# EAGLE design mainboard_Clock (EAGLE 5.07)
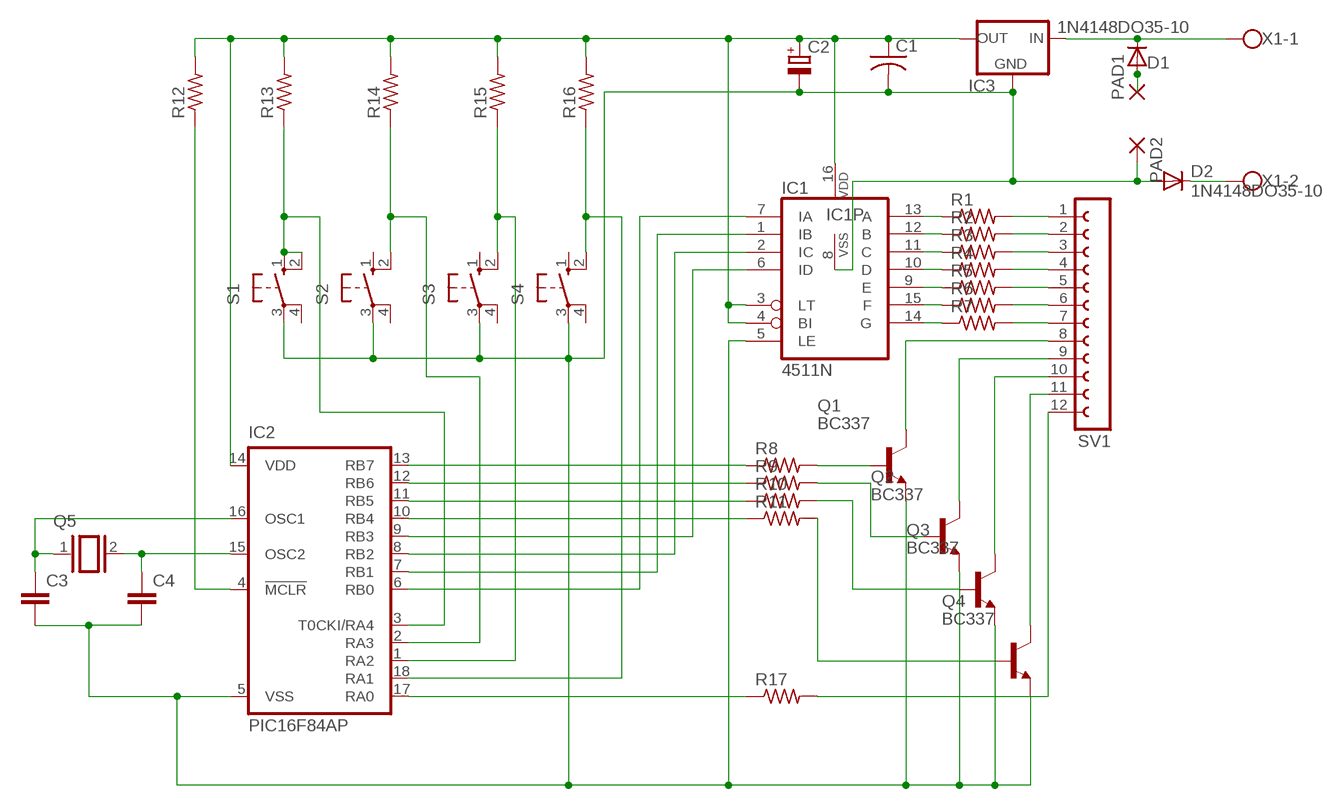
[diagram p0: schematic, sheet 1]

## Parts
C1  C-US050-025X075  [C050-025X075]
C2  CPOL-EUE5-8.5  [E5-8,5]
C3  C2.5/2  [C2.5-2]
C4  C2.5/2  [C2.5-2]
D1  1N4148DO35-10  [DO35-10]
D2  1N4148DO35-10  [DO35-10]
IC1  4511N  [DIL16]
IC2  PIC16F84AP  [DIL18]
IC3  78XXS  [78XXS]
PAD1  3,81/1,4  [3,81/1,4]
PAD2  3,81/1,4  [3,81/1,4]
Q1  BC337  [TO92]
Q2  BC337  [TO92]
Q3  BC337  [TO92]
Q4  BC337  [TO92]
Q5  XTAL/S  [QS]
R1  R-US_0207/10  [0207/10]
R2  R-US_0207/10  [0207/10]
R3  R-US_0207/10  [0207/10]
R4  R-US_0207/10  [0207/10]
R5  R-US_0207/10  [0207/10]
R6  R-US_0207/10  [0207/10]
R7  R-US_0207/10  [0207/10]
R8  R-US_0207/10  [0207/10]
R9  R-US_0207/10  [0207/10]
R10  R-US_0207/10  [0207/10]
R11  R-US_0207/10  [0207/10]
R12  R-US_0207/10  [0207/10]
R13  R-US_0207/10  [0207/10]
R14  R-US_0207/10  [0207/10]
R15  R-US_0207/10  [0207/10]
R16  R-US_0207/10  [0207/10]
R17  R-US_0207/10  [0207/10]
S1  10-XX  [B3F-10XX]
S2  10-XX  [B3F-10XX]
S3  10-XX  [B3F-10XX]
S4  10-XX  [B3F-10XX]
SV1  FE12-1  [FE12]
X1  W237-102  [W237-102]

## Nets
N$1: Q1.3(C) SV1.8
N$2: Q3.2(B) R10.2
N$3: Q3.3(C) SV1.10
N$4: IC2.11(RB5) R10.1
N$5: IC1.13(A) R1.1
N$6: IC1.12(B) R2.1
N$7: IC1.11(C) R3.1
N$8: IC1.10(D) R4.1
N$9: IC1.9(E) R5.1
N$10: IC1.15(F) R6.1
N$11: IC1.14(G) R7.1
N$12: Q1.2(B) R8.2
N$13: Q2.2(B) R9.2
N$14: Q4.3(C) SV1.11
N$23: R1.2 SV1.1
N$24: IC2.13(RB7) R8.1
N$25: IC2.12(RB6) R9.1
N$26: Q2.3(C) SV1.9
N$28: C1.1 C2.+ IC1.3(LT) IC1.4(BI) IC1.16(VDD) IC2.14(VDD) IC3.OUT R12.2 R13.2 R14.2 R15.2 R16.2
N$29: IC1.7(IA) IC2.6(RB0)
N$30: IC1.1(IB) IC2.7(RB1)
N$31: IC1.2(IC) IC2.8(RB2)
N$32: IC1.6(ID) IC2.9(RB3)
N$33: Q4.2(B) R11.2
N$34: C1.2 C2.- C3.2 C4.2 D2.A IC1.5(LE) IC1.8(VSS) IC2.5(VSS) IC3.GND PAD2.1(P) Q1.1(E) Q2.1(E) Q3.1(E) Q4.1(E) S1.3(P) S2.3(P) S3.3(P) S4.3(P)
N$35: D1.C IC3.IN X1.1
N$36: D1.A PAD1.1(P)
N$37: D2.C X1.2
N$38: IC2.17(RA0) R17.1
N$39: IC2.4(!MCLR) R12.1
N$40: IC2.3(T0CKI/RA4) R13.1 S1.1(S) S1.2(S1)
N$41: IC2.2(RA3) R14.1 S2.2(S1)
N$42: IC2.1(RA2) R15.1 S3.2(S1)
N$43: IC2.18(RA1) R16.1 S4.2(S1)
N$45: C4.1 IC2.15(OSC2) Q5.2
N$46: C3.1 IC2.16(OSC1) Q5.1
N$47: R2.2 SV1.2
N$48: R3.2 SV1.3
N$49: R4.2 SV1.4
N$50: R5.2 SV1.5
N$51: R6.2 SV1.6
N$52: R7.2 SV1.7
N$56: IC2.10(RB4) R11.1
N$57: R17.2 SV1.12
Unconnected: S1.4(P1) S2.1(S) S2.4(P1) S3.1(S) S3.4(P1) S4.1(S) S4.4(P1)

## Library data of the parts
C1 = resistor:C-US: CAPACITOR, American symbol
C2 = resistor:CPOL-EU: POLARIZED CAPACITOR, European symbol
C3 C4 = capacitor-wima:C: CAPACITOR
D1 D2 = diode:1N4148: DIODE
IC1 = 45xx:4511: BCD to 7-segment LATCH/DECODER/DRIVER
IC2 = microchip:PIC16F8*: MICROCONTROLLER 8-Bit PIC16F8X Family - CMOS Flash/EEPROM Pin Compatible : PIC16F83, PIC16CR83, PIC16F84A, PIC16CR84 see also PIC16C*
IC3 = v-reg:78XXS: VOLTAGE REGULATOR
PAD1 PAD2 = wirepad:3,81/1,4: THROUGH-HOLE PAD
Q1-Q4 = transistor-npn:BC337*: NPN Transistor
Q5 = special:XTAL/S: CRYSTAL
R1-R17 = resistor:R-US_: RESISTOR, American symbol
S1-S4 = switch-omron:10-XX: OMRON SWITCH
SV1 = con-lsta:FE12-1: FEMALE HEADER
X1 = con-wago-500:W237-102: WAGO SCREW CLAMP

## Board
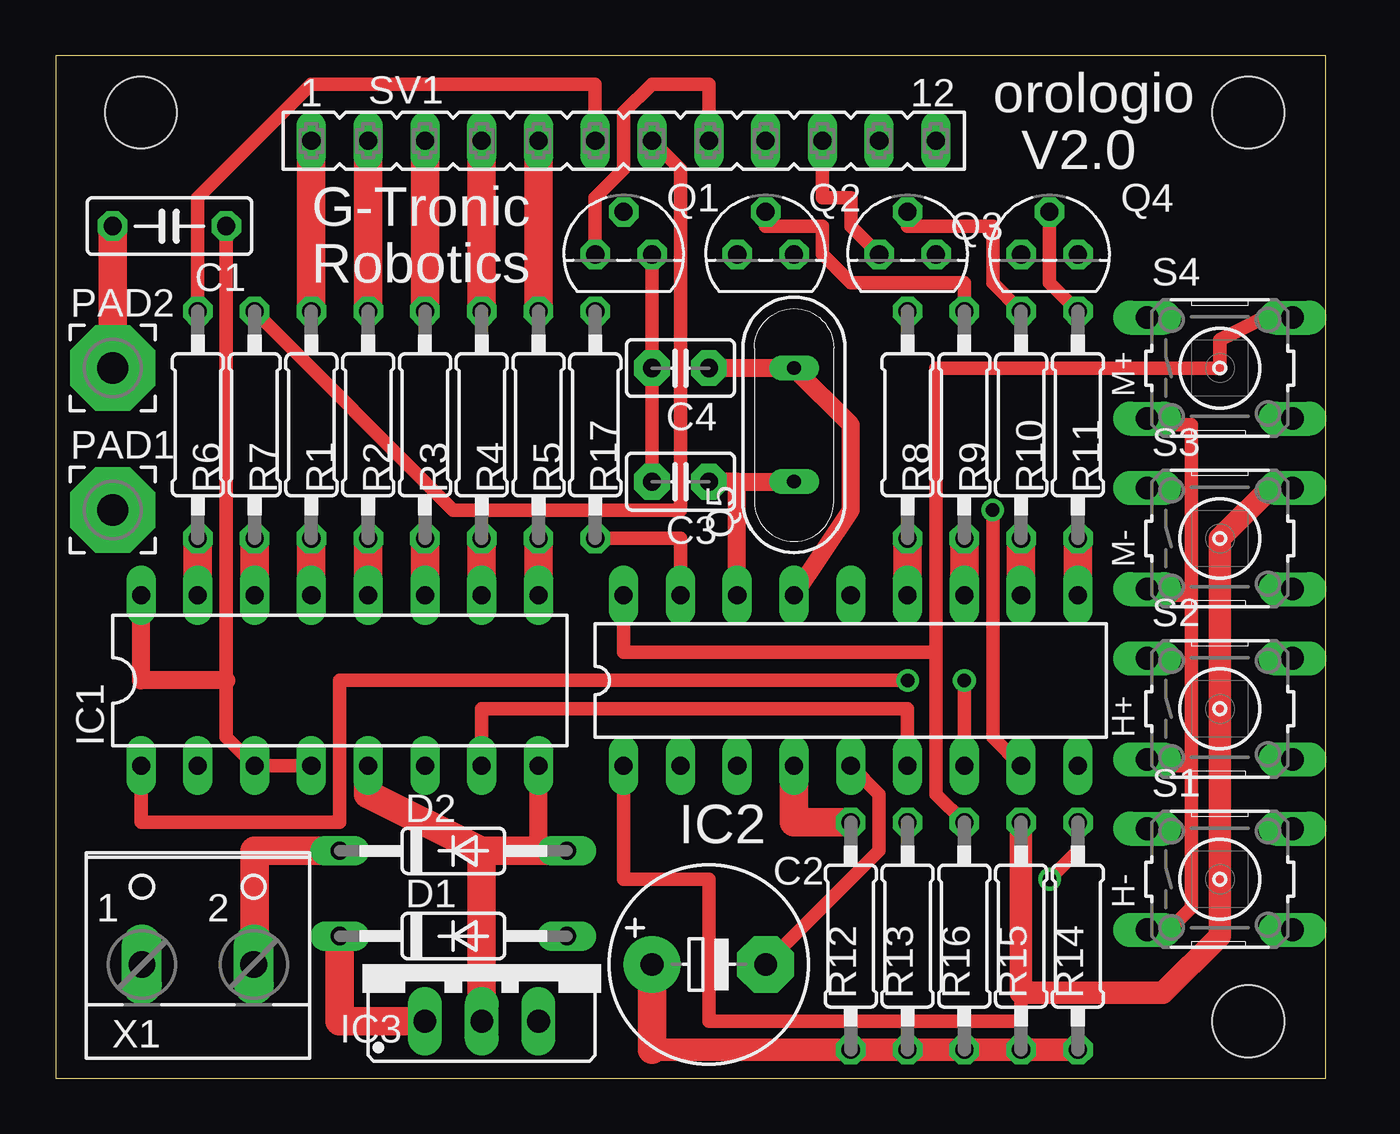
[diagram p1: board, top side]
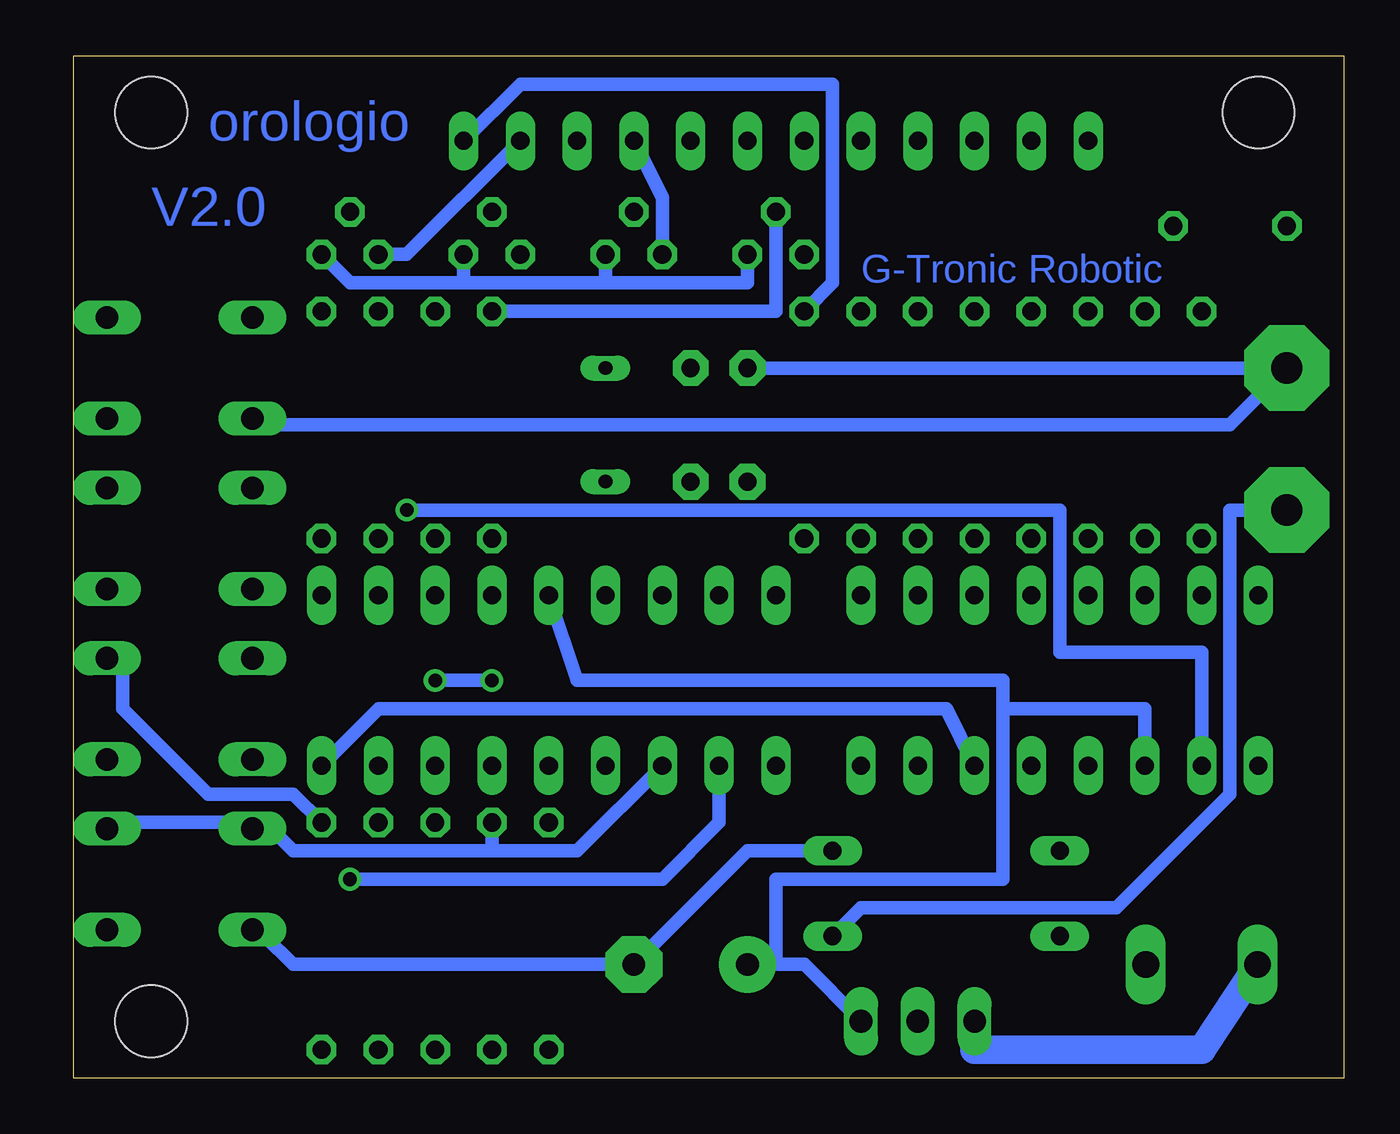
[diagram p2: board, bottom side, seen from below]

Size 56.82 x 45.71 mm. Coordinates in mm from the lower left corner, seen from the top.
Outline: 0,0 56.82,0 56.82,45.71 0,45.71 0,0
Copper layers (1*16): Top 0.035mm / dielectric 1.5mm / Bottom 0.035mm
Design rules "default": minimum track width 10mil, minimum drill 24mil, track to track 8mil, track to pad 8mil, pad to pad 8mil, via to via 8mil, smd to smd 8mil, copper to edge 40mil, drill to drill 8mil, minimum pad ring 10mil, minimum via ring 8mil, stop-mask expansion 4mil, vias tented up to drill 0mil, thermal gap 10mil
Holes 3.2 mm at 53.34,43.18 3.81,43.18 53.34,2.54

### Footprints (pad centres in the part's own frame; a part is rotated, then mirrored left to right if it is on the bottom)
C050-025X075 = drill 0.813 octagon: 1 -2.54,0; 2 2.54,0
E5-8,5 = drill 1.016 pad 2.54 round: + -2.54,0 | drill 1.016 pad 2.54 octagon: - 2.54,0
C2.5-2 = drill 0.813 pad 1.6 octagon: 1 -1.27,0; 2 1.27,0
DO35-10 = drill 0.813 long: A 5.08,0; C -5.08,0
DIL16 = drill 0.813 long: 1 -8.89,-3.81; 2 -6.35,-3.81; 3 -3.81,-3.81; 4 -1.27,-3.81; 5 1.27,-3.81; 6 3.81,-3.81; 7 6.35,-3.81; 8 8.89,-3.81; 9 8.89,3.81; 10 6.35,3.81; 11 3.81,3.81; 12 1.27,3.81; 13 -1.27,3.81; 14 -3.81,3.81; 15 -6.35,3.81; 16 -8.89,3.81
DIL18 = drill 0.813 long: 1 -10.16,-3.81; 2 -7.62,-3.81; 3 -5.08,-3.81; 4 -2.54,-3.81; 5 0,-3.81; 6 2.54,-3.81; 7 5.08,-3.81; 8 7.62,-3.81; 9 10.16,-3.81; 10 10.16,3.81; 11 7.62,3.81; 12 5.08,3.81; 13 2.54,3.81; 14 0,3.81; 15 -2.54,3.81; 16 -5.08,3.81; 17 -7.62,3.81; 18 -10.16,3.81
78XXS = drill 1.016 long: GND 0,-2.54; IN -2.54,-2.54; OUT 2.54,-2.54
3,81/1,4 = drill 1.397 pad 3.81 octagon: 1 0,0
TO92 = drill 0.813 octagon: 1 1.27,0; 2 0,1.905; 3 -1.27,0
QS = drill 0.61 long: 1 -2.54,0; 2 2.54,0
0207/10 = drill 0.813 octagon: 1 -5.08,0; 2 5.08,0
B3F-10XX = drill 1.016 long: 1 -3.251,2.261; 2 3.251,2.261; 3 -3.251,-2.261; 4 3.251,-2.261
FE12 = drill 0.813 long: 1 -13.97,0; 2 -11.43,0; 3 -8.89,0; 4 -6.35,0; 5 -3.81,0; 6 -1.27,0; 7 1.27,0; 8 3.81,0; 9 6.35,0; 10 8.89,0; 11 11.43,0; 12 13.97,0
W237-102 = drill 1.194 long: 1 -2.5,-1.27; 2 2.5,-1.27

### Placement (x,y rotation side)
C1  5.08,38.1 180 top
C2  29.21,5.08 0 top
C3  27.94,26.67 180 top
C4  27.94,31.75 180 top
D1  17.78,6.35 0 top
D2  17.78,10.16 0 top
IC1  12.7,17.78 0 top
IC2  35.56,17.78 0 top
IC3  19.05,5.08 0 top
PAD1  2.54,25.4 0 top
PAD2  2.54,31.75 0 top
Q1  25.4,36.83 0 top
Q2  31.75,36.83 0 top
Q3  38.1,36.83 0 top
Q4  44.45,36.83 0 top
Q5  33.02,29.21 90 top
R1  11.43,29.21 90 top
R2  13.97,29.21 90 top
R3  16.51,29.21 90 top
R4  19.05,29.21 90 top
R5  21.59,29.21 90 top
R6  6.35,29.21 90 top
R7  8.89,29.21 90 top
R8  38.1,29.21 90 top
R9  40.64,29.21 90 top
R10  43.18,29.21 90 top
R11  45.72,29.21 90 top
R12  35.56,6.35 270 top
R13  38.1,6.35 270 top
R14  45.72,6.35 270 top
R15  43.18,6.35 270 top
R16  40.64,6.35 270 top
R17  24.13,29.21 90 top
S1  52.07,8.89 0 top
S2  52.07,16.51 0 top
S3  52.07,24.13 0 top
S4  52.07,31.75 0 top
SV1  25.4,41.91 0 top
X1  6.35,6.35 0 top

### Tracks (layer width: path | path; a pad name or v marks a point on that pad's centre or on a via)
N$1
  Top 0.61: Q1.3 24.13,39.37 25.4,40.64 25.4,43.18 26.67,44.45 29.21,44.45 SV1.8
N$2
  Top 0.61: R10.2 41.91,35.56 41.91,38.1 38.1,38.1 Q3.2
N$3
  Top 0.61: Q3.3 35.56,38.1 35.56,39.37 34.29,39.37 SV1.10
N$4
  Top 1.27: IC2.11 R10.1
N$5
  Top 1.27: IC1.13 R1.1
N$6
  Top 1.27: IC1.12 R2.1
N$7
  Top 1.27: IC1.11 R3.1
N$8
  Top 1.27: IC1.10 R4.1
N$9
  Top 1.27: IC1.9 R5.1
N$10
  Top 1.27: IC1.15 R6.1
N$11
  Top 1.27: IC1.14 R7.1
N$12
  Bottom 0.61: R8.2 25.4,34.29 Q1.2
N$13
  Top 0.61: R9.2 40.64,35.56 35.56,35.56 34.29,36.83 34.29,38.1 31.75,38.1 Q2.2
N$14
  Bottom 0.61: SV1.11 41.91,36.83 Q4.3
N$23
  Top 1.27: R1.2 SV1.1
N$24
  Top 1.27: IC2.13 R8.1
N$25
  Top 1.27: IC2.12 R9.1
N$26
  Bottom 0.61: Q2.3 30.48,39.37 SV1.9
N$28
  Top 0.61: C1.1 7.62,17.78 7.62,15.24 IC1.3 IC1.4
  Top 0.813: 7.62,17.78 3.81,17.78 IC1.16
  Top 1.016: R14.2 R15.2 R16.2 R13.2 R12.2 26.67,1.27
  Top 1.27: C2.+ 26.67,1.27
  Bottom 0.61: IC3.OUT 24.13,5.08 25.4,5.08 | 25.4,5.08 C2.+ | IC2.14 34.29,17.78 15.24,17.78 15.24,16.51 | 25.4,5.08 25.4,8.89 15.24,8.89 15.24,16.51 | IC1.3 8.89,16.51 15.24,16.51
N$29
  Top 0.61: IC1.7 19.05,16.51 38.1,16.51 IC2.6
N$30  (via drill 0.61)
  Top 0.61: IC1.1 3.81,11.43 12.7,11.43 12.7,17.78 v38.1,17.78 | v40.64,17.78 IC2.7
  Bottom 0.61: v38.1,17.78 v40.64,17.78
N$31  (via drill 0.61)
  Top 0.61: v41.91,25.4 41.91,15.24 IC2.8
  Bottom 0.61: IC1.2 6.35,19.05 12.7,19.05 12.7,25.4 v41.91,25.4
N$32
  Bottom 0.61: IC1.6 17.78,16.51 43.18,16.51 IC2.9
N$33
  Top 0.61: R11.2 44.45,35.56 Q4.2
N$34
  Top 0.61: Q1.1 C4.2 C3.2 | IC2.5 36.83,12.7 36.83,10.16 C2.- | 50.8,13.97 49.53,13.97 S2.3 | 50.8,13.97 50.8,7.62 49.53,6.35 S1.3 | 50.8,21.59 49.53,21.59 S3.3 | 50.8,13.97 50.8,21.59 | 50.8,21.59 50.8,29.21 49.53,29.21 S4.3
  Top 0.813: 21.59,10.16 IC1.8
  Top 1.27: PAD2.1 C1.2 | 19.05,10.16 21.59,10.16 D2.A | IC3.GND 19.05,10.16 | 19.05,10.16 13.97,12.7 IC1.5
  Bottom 0.61: 33.02,35.56 Q2.1 | 33.02,35.56 26.67,35.56 Q1.1 | 39.37,35.56 Q3.1 | 33.02,35.56 39.37,35.56 | Q4.1 44.45,35.56 39.37,35.56 | C4.2 PAD2.1 5.08,29.21 48.26,29.21 S4.3 | S1.3 48.26,6.35 46.99,5.08 C2.- 26.67,10.16 D2.A
N$35
  Top 1.27: IC3.IN 12.7,2.54 D1.C
  Bottom 0.254: 3.81,5.08 X1.1
  Bottom 1.27: 3.81,5.08 6.35,1.27 16.51,1.27 IC3.IN
N$36
  Bottom 0.61: D1.A 21.59,7.62 10.16,7.62 5.08,12.7 5.08,25.4 PAD1.1
N$37
  Top 0.254: X1.2 8.89,5.08
  Top 1.27: D2.C 8.89,10.16 8.89,5.08
N$38
  Top 0.61: R17.1 27.94,24.13 IC2.17
N$39
  Top 1.27: R12.1 33.02,11.43 IC2.4
N$40
  Bottom 0.61: S1.2 54.61,11.43 49.53,11.43 S1.1 48.26,11.43 46.99,10.16 38.1,10.16 | IC2.3 34.29,10.16 38.1,10.16 | 38.1,10.16 R13.1
N$41  (via drill 0.61)
  Top 0.61: v44.45,8.89 45.72,10.16 R14.1
  Bottom 0.61: IC2.2 27.94,11.43 30.48,8.89 v44.45,8.89 | R14.1 46.99,12.7 50.8,12.7 54.61,16.51 54.61,19.05 S2.2
N$42
  Top 0.61: IC2.1 25.4,8.89 29.21,8.89 29.21,2.54 43.18,2.54 43.18,3.81
  Top 1.016: R15.1 43.18,3.81 49.53,3.81 52.07,6.35 52.07,24.13 54.61,26.67 S3.2
N$43
  Top 0.61: IC2.18 25.4,19.05 39.37,19.05 | 39.37,19.05 39.37,12.7 R16.1 | 39.37,19.05 39.37,31.75 52.07,31.75 52.07,33.02 54.61,34.29 S4.2
N$45
  Top 0.813: C4.1 Q5.2 35.56,29.21 35.56,25.4 IC2.15
N$46
  Top 0.813: 30.48,26.67 C3.1 | 30.48,26.67 Q5.1 | IC2.16 30.48,26.67
N$47
  Top 1.27: R2.2 SV1.2
N$48
  Top 1.27: R3.2 SV1.3
N$49
  Top 1.27: R4.2 SV1.4
N$50
  Top 1.27: R5.2 SV1.5
N$51
  Top 0.61: R6.2 6.35,39.37 11.43,44.45 24.13,44.45 SV1.6
N$52
  Top 0.61: R7.2 17.78,25.4 27.94,25.4 27.94,40.64 SV1.7
N$56
  Top 1.27: IC2.10 R11.1
N$57
  Bottom 0.61: R17.2 22.86,35.56 22.86,44.45 36.83,44.45 SV1.12

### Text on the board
Bottom: orologio | V2.0 | G-Tronic Robotic
tNames: orologio | V2.0 | G-Tronic | Robotics | M+ | M- | H+ | H-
